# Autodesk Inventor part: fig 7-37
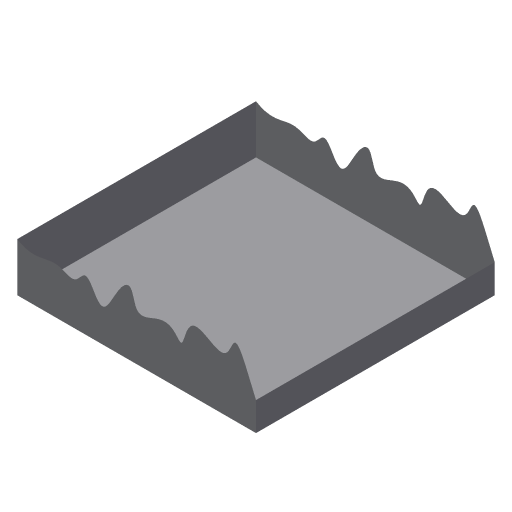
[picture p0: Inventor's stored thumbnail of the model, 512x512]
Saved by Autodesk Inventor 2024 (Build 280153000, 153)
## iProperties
Shininess: 64.0
Length Units: 11269
Angle Units: 11279
Time Units: 11290
Mass Units: 11283
Length Display Precision: 3
Angle Display Precision: 2
Compacted: True
Part Number: fig 7-37
Document SubType Name: Modeling
Created: 2002-12
Designer: deepak
Density: 1 g/cm^3
Material: Generic
Appearance: Default
Density: 0.0
Volumn: 0.0
Area: 0.0
PropertySet Name: Model Information
Control State: 0
Master: False
Checked Out: False
Author: deepak
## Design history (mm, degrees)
sketch "Sketch1"
  geometry: L1 (-32.188, 30.089)-(27.812, 30.089); L2 (27.812, 30.089)-(27.812, -29.911); L3 (27.812, -29.911)-(-32.188, -29.911); L4 (-32.188, -29.911)-(-32.188, 30.089)
  constraints: 8 end point, 2 parallel, 1 horizontal, 1 perpendicular
  dimensions: "d0" = 60 distance of L1.start L1.end; "d1" = 60 distance of L3.end L1.start
extrude "Extrusion1" new body sketch "Sketch1" stored distance "d2" = 20; taper "d3" = 0 deg
sketch "Sketch2"
  geometry: 17 further points
  constraints: 17 other
extrude_surface "ExtrusionSrf1" sketch "Sketch2" dims "d4" = 70, "d5" = 0
split "Split1"
delete_face "Delete Face1"
body "Srf1"
node "Sketch5"
body "Srf2"
